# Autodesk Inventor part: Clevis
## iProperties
Author: Administrator
Shininess: 76.0
PropertySet Name: _Private Model Information
Created: 2001-01
Part Number: Clevis
Material: Steel, Mild
Document SubType Name: Modeling
Designer: Administrator
Control State: 0
Master: False
Checked Out: False
PropertySet Name: Design Tracking Control
Density: 7.86
Volumn: 4.610495639398596
Area: 35.132835442150075
PropertySet Name: Model Information
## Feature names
1. Revolution1
2. Sweep2
3. Revolution3
4. Extrusion2
5. Fillet1
